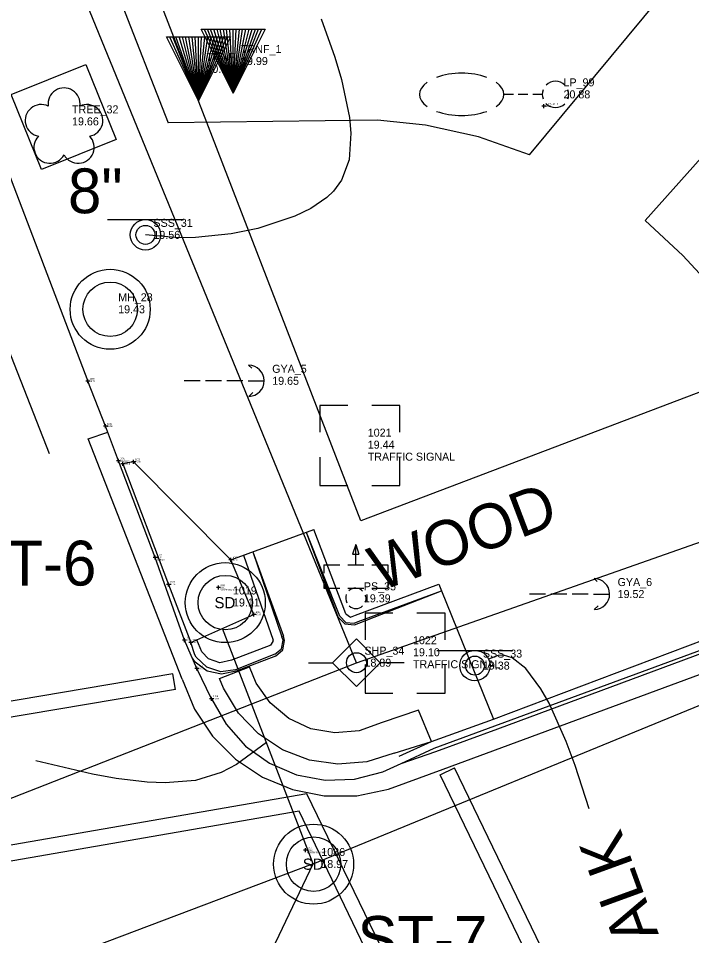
# Model space of a CAD drawing. Extents: x 509744 to 512285, y 1314862 to 1316822.
# Drawn here: x 510565.2 to 510607.3, y 1315469.6 to 1315526.9 of the extents above; entities that cross this region are included whole.
import ezdxf

# ---------------------------------------------------------------- set-up
doc = ezdxf.new("R2010")
doc.units = 0
for name, color, linetype in [('CGBack_ep', 7, 'Continuous'), ('CGep_ep', 7, 'Continuous'), ('CGFace_ep', 7, 'Continuous'), ('CurbRampWarning_ep', 7, 'Continuous'), ('ElecAer_ep', 7, 'Continuous'), ('GroundShot_ep', 7, 'Continuous'), ('GuyWireAnchor_ep', 7, 'Continuous'), ('InletCurb_ep', 7, 'Continuous'), ('LARWLine_ep', 7, 'Continuous'), ('Luminaire_ep', 7, 'Continuous'), ('ManholeSW_ep', 7, 'Continuous'), ('ManholeUnknown_ep', 7, 'Continuous'), ('NonPlottingEle_dp', 7, 'Continuous'), ('PavtAsphalt_ep', 7, 'Continuous'), ('PavtBrick_ep', 7, 'Continuous'), ('PavtConcrete_ep', 7, 'Continuous'), ('PedSignal_ep', 7, 'Continuous'), ('PipeCulvert_ep', 7, 'Continuous'), ('PMRK_ep', 7, 'Continuous'), ('PointLocator_ep', 7, 'Continuous'), ('PoleShared_ep', 7, 'Continuous'), ('PullBox_ep', 7, 'Continuous'), ('RWLine_ep', 7, 'Continuous'), ('SidewalkBack_ep', 7, 'Continuous'), ('SignSingle_ep', 7, 'Continuous'), ('TextElevLabel', 7, 'Continuous'), ('TextPtLabel', 7, 'Continuous'), ('TextSurveyLabel', 7, 'Continuous'), ('TextTopoLabel_ep', 7, 'Continuous'), ('TextUtilLabel_ep', 7, 'Continuous'), ('Transformer_ep', 7, 'Continuous'), ('Tree_ep', 7, 'Continuous')]:
    doc.layers.add(name, color=color, linetype=linetype)

msp = doc.modelspace()

# ---------------------------------------------------------------- linework, layer by layer
at = {"layer": 'CGBack_ep'}
for p, q in [((510585.65, 1315489.734), (510583.665, 1315494.996)), ((510579.27, 1315493.389), (510581.107, 1315488.075)), ((510586.268, 1315489.638), (510591.47, 1315491.58)), ((510576.648, 1315487.348), (510576.337, 1315488.109)), ((510580.965, 1315487.781), (510578.52, 1315486.825))]:
    msp.add_line(p, q, dxfattribs=at)
for points in [[(510594.893, 1315483.143), (510610.348, 1315488.985), (510663.591, 1315508.715), (510705.599, 1315524.411)], [(510585.65, 1315489.734), (510585.949, 1315489.517), (510586.268, 1315489.638)], [(510580.965, 1315487.781), (510581.124, 1315488.005), (510581.107, 1315488.075)], [(510578.52, 1315486.825), (510577.785, 1315486.67), (510577.074, 1315486.908), (510576.648, 1315487.348)], [(510588.986, 1315480.839), (510591.012, 1315481.745), (510594.893, 1315483.143)]]:
    msp.add_lwpolyline(points, dxfattribs=at)
at = {"layer": 'CGep_ep'}
for p, q in [((510585.166, 1315489.528), (510583.19, 1315494.823)), ((510579.848, 1315493.6), (510581.752, 1315488.328)), ((510586.474, 1315489.141), (510591.64, 1315491.161)), ((510581.26, 1315487.093), (510578.796, 1315486.152))]:
    msp.add_line(p, q, dxfattribs=at)
for points in [[(510543.895, 1315570.868), (510561.924, 1315524.191), (510569.541, 1315504.268)], [(510595.152, 1315482.536), (510610.663, 1315488.302), (510663.851, 1315507.999), (510703.628, 1315522.764)], [(510571.444, 1315499.295), (510570.637, 1315501.459), (510569.541, 1315504.268)], [(510577.267, 1315484.427), (510576.335, 1315486.321), (510575.57, 1315488.095), (510573.746, 1315493.259), (510571.444, 1315499.295)], [(510585.166, 1315489.528), (510585.603, 1315489.109), (510586.204, 1315489.039), (510586.474, 1315489.141)], [(510581.26, 1315487.093), (510581.708, 1315487.475), (510581.828, 1315488.058), (510581.752, 1315488.328)], [(510578.796, 1315486.152), (510577.891, 1315485.954), (510576.986, 1315486.152), (510576.245, 1315486.709), (510576.064, 1315486.95)], [(510577.267, 1315484.427), (510578.167, 1315482.83), (510579.39, 1315481.465), (510580.88, 1315480.397), (510582.566, 1315479.676), (510584.367, 1315479.337), (510586.2, 1315479.395), (510587.976, 1315479.847), (510589.106, 1315480.369)], [(510589.106, 1315480.369), (510591.271, 1315481.13), (510595.152, 1315482.536)]]:
    msp.add_lwpolyline(points, dxfattribs=at)
at = {"layer": 'CGFace_ep'}
for p, q in [((510585.276, 1315489.575), (510583.19, 1315494.823)), ((510579.848, 1315493.6), (510581.654, 1315488.289)), ((510586.425, 1315489.259), (510591.64, 1315491.161)), ((510576.209, 1315487.162), (510575.975, 1315487.949)), ((510581.213, 1315487.203), (510578.767, 1315486.222))]:
    msp.add_line(p, q, dxfattribs=at)
for points in [[(510591.183, 1315481.338), (510610.582, 1315488.477), (510663.775, 1315508.208), (510705.705, 1315523.824)], [(510585.276, 1315489.575), (510585.648, 1315489.183), (510586.186, 1315489.139), (510586.425, 1315489.259)], [(510581.213, 1315487.203), (510581.637, 1315487.543), (510581.729, 1315488.079), (510581.654, 1315488.289)], [(510578.767, 1315486.222), (510577.85, 1315486.116), (510576.972, 1315486.403), (510576.293, 1315487.031), (510576.209, 1315487.162)], [(510589.106, 1315480.369), (510591.183, 1315481.338), (510591.183, 1315481.338)]]:
    msp.add_lwpolyline(points, dxfattribs=at)
at = {"layer": 'CurbRampWarning_ep'}
msp.add_line((510577.761, 1315485.68), (510579.628, 1315486.422), dxfattribs=at)
for points in [[(510587.925, 1315482.947), (510586.494, 1315482.421), (510584.976, 1315482.283), (510583.474, 1315482.543), (510582.091, 1315483.183), (510580.92, 1315484.16), (510580.043, 1315485.407), (510579.628, 1315486.422)], [(510588.684, 1315481.016), (510586.963, 1315480.482), (510585.165, 1315480.339), (510583.38, 1315480.594), (510581.694, 1315481.235), (510580.191, 1315482.23), (510578.943, 1315483.531), (510578.012, 1315485.075), (510577.761, 1315485.68)], [(510588.684, 1315481.016), (510591.012, 1315481.745), (510590.189, 1315483.701), (510587.925, 1315482.947)]]:
    msp.add_lwpolyline(points, dxfattribs=at)
at = {"layer": 'ElecAer_ep'}
msp.add_line((510586.32, 1315486.678), (510545.674, 1315586.019), dxfattribs=at)
msp.add_lwpolyline([(510459.752, 1315437.864), (510522.46, 1315461.639), (510586.32, 1315486.678), (510629.501, 1315501.863)], dxfattribs=at)
at = {"layer": 'GroundShot_ep'}
for p, q in [((510598.157, 1315521.461), (510597.907, 1315521.461)), ((510598.032, 1315521.336), (510598.032, 1315521.586))]:
    msp.add_line(p, q, dxfattribs=at)
at = {"layer": 'GuyWireAnchor_ep'}
for p, q in [((510579.582, 1315505.268), (510579.775, 1315505.075)), ((510575.555, 1315504.304), (510576.555, 1315504.304)), ((510576.889, 1315504.304), (510577.889, 1315504.304)), ((510578.222, 1315504.304), (510579.222, 1315504.304)), ((510579.555, 1315504.295), (510580.555, 1315504.295)), ((510579.597, 1315503.322), (510579.835, 1315503.555)), ((510601.166, 1315491.939), (510601.359, 1315491.746)), ((510597.139, 1315490.976), (510598.139, 1315490.976)), ((510598.473, 1315490.976), (510599.473, 1315490.976)), ((510599.806, 1315490.976), (510600.806, 1315490.976)), ((510601.139, 1315490.966), (510602.139, 1315490.966)), ((510601.181, 1315489.993), (510601.419, 1315490.226))]:
    msp.add_line(p, q, dxfattribs=at)
for centre in [(510579.582, 1315504.295), (510601.167, 1315490.966)]:
    msp.add_arc(centre, 0.973, 271.13997, 90.0059, dxfattribs=at)
at = {"layer": 'InletCurb_ep'}
msp.add_lwpolyline([(510575.975, 1315487.949), (510579.907, 1315489.683), (510578.469, 1315493.096), (510572.386, 1315499.226), (510571.727, 1315499.099), (510574.574, 1315491.574)], close=True, dxfattribs=at)
at = {"layer": 'LARWLine_ep'}
msp.add_line((510785.638, 1315571.205), (510586.597, 1315495.535), dxfattribs=at)
at = {"layer": 'Luminaire_ep'}
for p, q in [((510596.133, 1315522.197), (510595.533, 1315522.197)), ((510597.033, 1315522.197), (510596.433, 1315522.197)), ((510597.933, 1315522.197), (510597.333, 1315522.197))]:
    msp.add_line(p, q, dxfattribs=at)
for start, end in [(45, 135), (159.91155, 200.08845), (339.91155, 20.08845), (225, 315)]:
    msp.add_arc((510598.758, 1315522.197), 0.825, start, end, dxfattribs=at)
for start_param, end_param in [(4.075781, 5.348997), (5.668326, 6.898045), (2.526733, 3.756452), (0.934187, 2.207405)]:
    msp.add_ellipse((510592.893, 1315522.197), major_axis=(-2.64, 0), ratio=0.5, start_param=start_param, end_param=end_param, dxfattribs=at)
at = {"layer": 'ManholeSW_ep'}
for centre, radius in [((510578.119, 1315490.43), 2.5), ((510578.119, 1315490.43), 1.7), ((510583.638, 1315474.086), 2.5), ((510583.638, 1315474.086), 1.7)]:
    msp.add_circle(centre, radius, dxfattribs=at)
at = {"layer": 'ManholeUnknown_ep'}
for radius in [2.5, 1.7]:
    msp.add_circle((510570.929, 1315508.765), radius, dxfattribs=at)
at = {"layer": 'NonPlottingEle_dp'}
msp.add_lwpolyline([(510580.693, 1315481.686), (510578.822, 1315480.307), (510577.863, 1315479.81), (510576.27, 1315479.322), (510574.362, 1315479.159), (510573.244, 1315479.205), (510571.309, 1315479.44), (510569.82, 1315479.71), (510566.283, 1315480.533)], dxfattribs=at)
at = {"layer": 'PavtAsphalt_ep'}
for p, q in [((510569.543, 1315500.658), (510570.773, 1315501.095)), ((510575.436, 1315485.651), (510569.543, 1315500.658))]:
    msp.add_line(p, q, dxfattribs=at)
for points in [[(510589.412, 1315479.166), (510591.739, 1315480.018), (510664.279, 1315506.821), (510711.133, 1315524.28), (510757.999, 1315541.71)], [(510575.436, 1315485.651), (510576.207, 1315483.777), (510577.33, 1315482.09), (510578.762, 1315480.655), (510580.447, 1315479.528), (510582.32, 1315478.753), (510584.309, 1315478.359), (510586.336, 1315478.363), (510588.323, 1315478.763), (510589.412, 1315479.166)]]:
    msp.add_lwpolyline(points, dxfattribs=at)
at = {"layer": 'PavtBrick_ep'}
msp.add_lwpolyline([(510564.744, 1315522.18), (510569.415, 1315524.064), (510571.309, 1315519.376), (510566.638, 1315517.492)], close=True, dxfattribs=at)
at = {"layer": 'PavtConcrete_ep'}
msp.add_line((510578.469, 1315493.096), (510583.665, 1315494.996), dxfattribs=at)
msp.add_lwpolyline([(510591.47, 1315491.58), (510591.64, 1315491.161), (510594.893, 1315483.143)], dxfattribs=at)
at = {"layer": 'PedSignal_ep'}
for p, q in [((510586.278, 1315494.063), (510586.08, 1315493.463)), ((510586.278, 1315492.788), (510586.278, 1315494.063)), ((510586.278, 1315494.063), (510586.476, 1315493.463)), ((510586.08, 1315493.463), (510586.476, 1315493.463)), ((510584.278, 1315492.788), (510585.278, 1315492.788)), ((510584.278, 1315492.788), (510584.278, 1315492.28)), ((510585.778, 1315492.788), (510586.778, 1315492.788)), ((510587.278, 1315492.788), (510588.278, 1315492.788)), ((510588.278, 1315492.788), (510588.278, 1315492.28)), ((510584.278, 1315491.845), (510584.278, 1315491.338)), ((510588.278, 1315491.845), (510588.278, 1315491.338)), ((510584.278, 1315491.338), (510585.278, 1315491.338)), ((510585.778, 1315491.338), (510586.778, 1315491.338)), ((510587.278, 1315491.338), (510588.278, 1315491.338))]:
    msp.add_line(p, q, dxfattribs=at)
for centre, radius, start, end in [((510586.421, 1315490.72), 0.766, 163.88316, 202.84976), ((510586.27, 1315490.721), 0.616, 45.06774, 132.92209), ((510586.496, 1315490.678), 0.437, 329.03624, 30.96376), ((510586.286, 1315490.68), 0.617, 227.10453, 312.89547)]:
    msp.add_arc(centre, radius, start, end, dxfattribs=at)
at = {"layer": 'PipeCulvert_ep'}
for p, q in [((510583.622, 1315474.096), (510705.621, 1315524.289)), ((510583.622, 1315474.096), (510577.941, 1315488.816)), ((510583.622, 1315474.096), (510465.136, 1315429.48)), ((510547.841, 1315399.532), (510583.622, 1315474.096))]:
    msp.add_line(p, q, dxfattribs=at)
at = {"layer": 'PMRK_ep'}
for p, q in [((510574.848, 1315485.98), (510522.318, 1315477.15)), ((510575.014, 1315484.994), (510574.848, 1315485.98)), ((510575.014, 1315484.994), (510522.484, 1315476.163)), ((510591.543, 1315479.665), (510592.443, 1315480.101)), ((510613.761, 1315436.1), (510592.443, 1315480.101)), ((510612.974, 1315435.431), (510591.543, 1315479.665)), ((510583.218, 1315478.489), (510525.97, 1315468.559)), ((510606.89, 1315429.644), (510583.218, 1315478.489)), ((510582.737, 1315477.39), (510526.141, 1315467.574)), ((510605.645, 1315429.919), (510582.737, 1315477.39))]:
    msp.add_line(p, q, dxfattribs=at)
msp.add_lwpolyline([(510540.07, 1315569.216), (510558.162, 1315522.566), (510567.115, 1315499.753)], dxfattribs=at)
at = {"layer": 'PointLocator_ep'}
for p, q in [((510569.666, 1315504.268), (510569.416, 1315504.268)), ((510569.541, 1315504.143), (510569.541, 1315504.393)), ((510570.762, 1315501.459), (510570.512, 1315501.459)), ((510570.637, 1315501.334), (510570.637, 1315501.584)), ((510571.569, 1315499.295), (510571.319, 1315499.295)), ((510571.444, 1315499.17), (510571.444, 1315499.42)), ((510571.852, 1315499.099), (510571.602, 1315499.099)), ((510571.727, 1315498.974), (510571.727, 1315499.224)), ((510572.511, 1315499.226), (510572.261, 1315499.226)), ((510572.386, 1315499.101), (510572.386, 1315499.351)), ((510573.871, 1315493.259), (510573.621, 1315493.259)), ((510573.746, 1315493.134), (510573.746, 1315493.384)), ((510578.469, 1315492.971), (510578.469, 1315493.221)), ((510578.594, 1315493.096), (510578.344, 1315493.096)), ((510574.699, 1315491.574), (510574.449, 1315491.574)), ((510574.574, 1315491.449), (510574.574, 1315491.699)), ((510577.694, 1315491.251), (510577.694, 1315491.501)), ((510577.819, 1315491.376), (510577.569, 1315491.376)), ((510579.907, 1315489.558), (510579.907, 1315489.808)), ((510580.032, 1315489.683), (510579.782, 1315489.683)), ((510575.695, 1315488.095), (510575.445, 1315488.095)), ((510575.57, 1315487.97), (510575.57, 1315488.22)), ((510575.975, 1315487.824), (510575.975, 1315488.074)), ((510576.1, 1315487.949), (510575.85, 1315487.949)), ((510576.46, 1315486.321), (510576.21, 1315486.321)), ((510576.335, 1315486.196), (510576.335, 1315486.446)), ((510577.392, 1315484.427), (510577.142, 1315484.427)), ((510577.267, 1315484.302), (510577.267, 1315484.552)), ((510583.251, 1315474.965), (510583.001, 1315474.965)), ((510583.126, 1315474.84), (510583.126, 1315475.09))]:
    msp.add_line(p, q, dxfattribs=at)
at = {"layer": 'PoleShared_ep'}
for p, q in [((510583.332, 1315486.678), (510584.832, 1315486.678)), ((510589.308, 1315486.678), (510587.808, 1315486.678))]:
    msp.add_line(p, q, dxfattribs=at)
msp.add_lwpolyline([(510584.832, 1315486.678), (510586.32, 1315488.166), (510587.808, 1315486.678), (510586.32, 1315485.19), (510584.832, 1315486.678)], dxfattribs=at)
msp.add_circle((510586.32, 1315486.678), 0.625, dxfattribs=at)
at = {"layer": 'PullBox_ep'}
for points in [[(510585.771, 1315502.753), (510584.038, 1315502.753), (510584.038, 1315501.077)], [(510589.033, 1315501.077), (510589.033, 1315502.753), (510587.271, 1315502.753)], [(510584.038, 1315499.526), (510584.038, 1315497.753)], [(510587.271, 1315497.753), (510589.033, 1315497.753), (510589.033, 1315499.526)], [(510584.038, 1315497.753), (510585.771, 1315497.753)], [(510588.6, 1315489.781), (510586.867, 1315489.781), (510586.867, 1315488.105)], [(510591.862, 1315488.105), (510591.862, 1315489.781), (510590.1, 1315489.781)], [(510586.867, 1315486.554), (510586.867, 1315484.781)], [(510590.1, 1315484.781), (510591.862, 1315484.781), (510591.862, 1315486.554)], [(510586.867, 1315484.781), (510588.6, 1315484.781)]]:
    msp.add_lwpolyline(points, dxfattribs=at)
at = {"layer": 'RWLine_ep'}
msp.add_line((510586.597, 1315495.535), (510509.14, 1315695.788), dxfattribs=at)
at = {"layer": 'SidewalkBack_ep'}
for p, q in [((510553.356, 1315574.956), (510574.551, 1315520.408)), ((510597.14, 1315518.424), (510609.121, 1315532.884)), ((510587.642, 1315520.588), (510574.551, 1315520.408))]:
    msp.add_line(p, q, dxfattribs=at)
for points in [[(510604.356, 1315514.305), (510608.727, 1315519.219), (510612.815, 1315524.375), (510615.556, 1315528.202)], [(510597.14, 1315518.424), (510593.938, 1315519.539), (510590.628, 1315520.27), (510587.642, 1315520.588)], [(510615.17, 1315501.264), (510612.668, 1315505.124), (510609.842, 1315508.751), (510606.711, 1315512.119), (510604.356, 1315514.305)]]:
    msp.add_lwpolyline(points, dxfattribs=at)
at = {"layer": 'SignSingle_ep'}
for p, q in [((510570.757, 1315514.366), (510575.507, 1315514.366)), ((510591.346, 1315487.446), (510596.096, 1315487.446))]:
    msp.add_line(p, q, dxfattribs=at)
for centre, radius in [((510573.132, 1315513.416), 0.95), ((510573.132, 1315513.416), 0.594), ((510593.721, 1315486.496), 0.95), ((510593.721, 1315486.496), 0.594)]:
    msp.add_circle(centre, radius, dxfattribs=at)
at = {"layer": 'TextTopoLabel_ep'}
for points in [[(510584.116, 1315526.912), (510584.962, 1315524.524), (510585.379, 1315523.127), (510585.88, 1315520.759), (510585.972, 1315519.766), (510585.86, 1315518.113), (510585.382, 1315516.833), (510584.878, 1315516.148), (510584.464, 1315515.75), (510583.466, 1315515.068), (510582.464, 1315514.579), (510580.149, 1315513.821), (510578.483, 1315513.484), (510576.267, 1315513.25), (510575.215, 1315513.228), (510573.132, 1315513.416)], [(510600.865, 1315477.552), (510599.983, 1315480.25), (510599.42, 1315481.759), (510598.352, 1315484.142), (510597.849, 1315485.041), (510596.903, 1315486.317), (510596.041, 1315486.985), (510595.514, 1315487.141), (510595.184, 1315487.136), (510594.575, 1315486.9)]]:
    msp.add_lwpolyline(points, dxfattribs=at)
at = {"layer": 'Transformer_ep'}
for p, q in [((510578.607, 1315522.281), (510576.607, 1315526.281)), ((510576.607, 1315526.281), (510580.607, 1315526.281)), ((510576.806, 1315526.281), (510578.607, 1315522.281)), ((510578.607, 1315522.281), (510577.005, 1315526.281)), ((510578.607, 1315522.281), (510577.204, 1315526.281)), ((510578.607, 1315522.281), (510577.407, 1315526.281)), ((510578.607, 1315522.281), (510577.607, 1315526.281)), ((510578.607, 1315522.281), (510577.806, 1315526.281)), ((510578.607, 1315522.281), (510578.005, 1315526.281)), ((510578.607, 1315522.281), (510578.208, 1315526.281)), ((510578.607, 1315522.281), (510578.407, 1315526.281)), ((510578.607, 1315522.281), (510578.806, 1315526.281)), ((510578.607, 1315522.281), (510579.005, 1315526.281)), ((510578.607, 1315522.281), (510579.204, 1315526.281)), ((510578.607, 1315522.281), (510579.407, 1315526.281)), ((510578.607, 1315522.281), (510579.806, 1315526.281)), ((510578.607, 1315522.281), (510580.009, 1315526.281)), ((510578.607, 1315522.281), (510580.204, 1315526.281)), ((510578.607, 1315522.281), (510580.403, 1315526.281)), ((510580.607, 1315526.281), (510578.607, 1315522.281)), ((510578.607, 1315522.281), (510578.607, 1315526.281)), ((510578.607, 1315522.281), (510579.607, 1315526.281)), ((510576.441, 1315521.788), (510574.441, 1315525.788)), ((510574.441, 1315525.788), (510578.441, 1315525.788)), ((510574.64, 1315525.788), (510576.441, 1315521.788)), ((510576.441, 1315521.788), (510574.84, 1315525.788)), ((510576.441, 1315521.788), (510575.039, 1315525.788)), ((510576.441, 1315521.788), (510575.242, 1315525.788)), ((510576.441, 1315521.788), (510575.441, 1315525.788)), ((510576.441, 1315521.788), (510575.64, 1315525.788)), ((510576.441, 1315521.788), (510575.84, 1315525.788)), ((510576.441, 1315521.788), (510576.043, 1315525.788)), ((510576.441, 1315521.788), (510576.242, 1315525.788)), ((510576.441, 1315521.788), (510576.64, 1315525.788)), ((510576.441, 1315521.788), (510576.84, 1315525.788)), ((510576.441, 1315521.788), (510577.039, 1315525.788)), ((510576.441, 1315521.788), (510577.242, 1315525.788)), ((510576.441, 1315521.788), (510577.64, 1315525.788)), ((510576.441, 1315521.788), (510577.844, 1315525.788)), ((510576.441, 1315521.788), (510578.039, 1315525.788)), ((510576.441, 1315521.788), (510578.238, 1315525.788)), ((510578.441, 1315525.788), (510576.441, 1315521.788)), ((510576.441, 1315521.788), (510576.441, 1315525.788)), ((510576.441, 1315521.788), (510577.441, 1315525.788))]:
    msp.add_line(p, q, dxfattribs=at)
at = {"layer": 'Tree_ep'}
for centre, start, end in [((510568.045, 1315521.602), 352.15457, 187.84543), ((510566.619, 1315520.565), 64.15457, 259.84543), ((510569.472, 1315520.565), 280.15457, 115.84543), ((510567.164, 1315518.888), 136.15457, 331.84543), ((510568.927, 1315518.888), 208.15457, 43.84543)]:
    msp.add_arc(centre, 1, start, end, dxfattribs=at)

# ---------------------------------------------------------------- texts
at = {"layer": 'ManholeSW_ep'}
for p in [(510577.447, 1315490.08), (510582.966, 1315473.736)]:
    msp.add_text('SD', height=0.7, dxfattribs=at).set_placement(p)
at = {"layer": 'NonPlottingEle_dp'}
for s, p in [('ST-6', (510561.95, 1315491.499)), ('ST-7', (510586.386, 1315468.044))]:
    msp.add_text(s, height=2.8, dxfattribs=at).set_placement(p)
at = {"layer": 'TextElevLabel'}
for s, height, p in [('19.99', 0.5, (510579.107, 1315524.031)), ('20.18', 0.5, (510576.941, 1315523.538)), ('20.88', 0.5, (510599.258, 1315521.947)), ('20.65', 0.1, (510598.132, 1315521.411)), ('19.66', 0.5, (510568.545, 1315520.259)), ('19.56', 0.5, (510573.632, 1315513.166)), ('19.43', 0.5, (510571.429, 1315508.515)), ('18.71', 0.1, (510569.641, 1315504.218)), ('19.65', 0.5, (510581.055, 1315504.045)), ('18.55', 0.1, (510570.737, 1315501.409)), ('19.44', 0.5, (510587.025, 1315500.053)), ('18.45', 0.1, (510571.544, 1315499.245)), ('19.06', 0.1, (510571.827, 1315499.049)), ('19.05', 0.1, (510572.486, 1315499.176)), ('18.34', 0.1, (510573.846, 1315493.209)), ('19.10', 0.1, (510578.569, 1315493.046)), ('19.08', 0.1, (510574.674, 1315491.524)), ('19.11', 0.1, (510577.794, 1315491.326)), ('19.39', 0.5, (510586.783, 1315490.45)), ('19.52', 0.5, (510602.639, 1315490.716)), ('19.11', 0.5, (510578.603, 1315490.19)), ('19.13', 0.1, (510580.007, 1315489.633)), ('18.32', 0.1, (510575.67, 1315488.045)), ('19.07', 0.1, (510576.075, 1315487.899)), ('19.10', 0.5, (510589.854, 1315487.081)), ('18.89', 0.5, (510586.82, 1315486.428)), ('18.54', 0.1, (510576.435, 1315486.271)), ('19.38', 0.5, (510594.221, 1315486.246)), ('18.69', 0.1, (510577.367, 1315484.377)), ('18.96', 0.1, (510583.226, 1315474.915)), ('18.97', 0.5, (510584.122, 1315473.846))]:
    msp.add_text(s, height=height, dxfattribs=at).set_placement(p)
at = {"layer": 'TextPtLabel'}
for s, height, p in [('TRNF', 0.5, (510576.941, 1315524.288)), ('TRNF_1', 0.5, (510579.107, 1315524.781)), ('LP_99', 0.5, (510599.258, 1315522.697)), ('TREE_32', 0.5, (510568.545, 1315521.009)), ('DEFAULT_3', 0.1, (510598.132, 1315521.561)), ('SSS_31', 0.5, (510573.632, 1315513.916)), ('MH_28', 0.5, (510571.429, 1315509.265)), ('GYA_5', 0.5, (510581.055, 1315504.795)), ('1035', 0.1, (510569.641, 1315504.368)), ('1034', 0.1, (510570.737, 1315501.559)), ('1021', 0.5, (510587.025, 1315500.803)), ('1033', 0.1, (510571.544, 1315499.395)), ('1027', 0.1, (510571.827, 1315499.199)), ('1026', 0.1, (510572.486, 1315499.326)), ('1032', 0.1, (510573.846, 1315493.359)), ('1025', 0.1, (510578.569, 1315493.196)), ('1028', 0.1, (510574.674, 1315491.674)), ('1020', 0.1, (510577.794, 1315491.476)), ('PS_35', 0.5, (510586.783, 1315491.2)), ('GYA_6', 0.5, (510602.639, 1315491.466)), ('1019', 0.5, (510578.603, 1315490.94)), ('1024', 0.1, (510580.007, 1315489.783)), ('1031', 0.1, (510575.67, 1315488.195)), ('1023', 0.1, (510576.075, 1315488.049)), ('1022', 0.5, (510589.854, 1315487.831)), ('SHP_34', 0.5, (510586.82, 1315487.178)), ('SSS_33', 0.5, (510594.221, 1315486.996)), ('1030', 0.1, (510576.435, 1315486.421)), ('1029', 0.1, (510577.367, 1315484.527)), ('1087', 0.1, (510583.226, 1315475.065)), ('1086', 0.5, (510584.122, 1315474.596))]:
    msp.add_text(s, height=height, dxfattribs=at).set_placement(p)
at = {"layer": 'TextSurveyLabel'}
for s, height, p in [('TRAFFIC SIGNAL', 0.5, (510587.025, 1315499.303)), ('THROAT', 0.1, (510573.846, 1315493.059)), ('NORTH RIM MHD6', 0.1, (510577.794, 1315491.176)), ('TRAFFIC SIGNAL', 0.5, (510589.854, 1315486.331)), ('NORTH RIM MHD7', 0.1, (510583.226, 1315474.765))]:
    msp.add_text(s, height=height, dxfattribs=at).set_placement(p)
at = {"layer": 'TextTopoLabel_ep'}
msp.add_text('8"', height=2.8, dxfattribs=at).set_placement((510568.295, 1315514.767))
msp.add_text('USE CROSSWALK', height=2.8, rotation=110.00644, dxfattribs=at).set_placement((510613.974, 1315445.668))
at = {"layer": 'TextUtilLabel_ep'}
msp.add_text('WOOD', height=2.8, rotation=20.77377, dxfattribs=at).set_placement((510587.8, 1315491.117))

doc.saveas('drawing.dxf')
